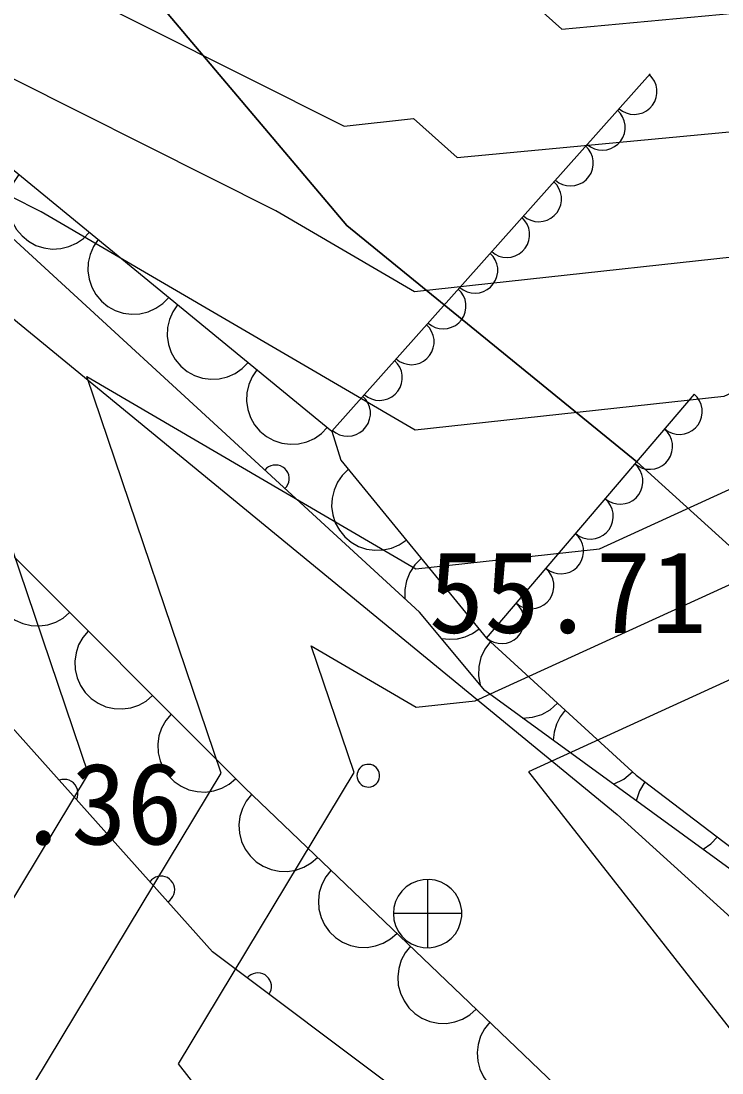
# Model space of a CAD drawing. Extents: x 42655 to 43811, y -141820 to -141156.
# Drawn here: x 43576.76 to 43584.45, y -141334.52 to -141322.99 of the extents above; entities that cross this region are included whole.
import ezdxf

# ---------------------------------------------------------------- set-up
doc = ezdxf.new("R2010")
doc.units = 0
for name, color, linetype in [('ZE_HICN', 7, 'Continuous'), ('ZE_LWCN', 7, 'Continuous'), ('地形', 7, 'Continuous'), ('現況道路ﾊｯﾁ', 7, 'Continuous')]:
    doc.layers.add(name, color=color, linetype=linetype)

msp = doc.modelspace()

# ---------------------------------------------------------------- linework, layer by layer
at = {"layer": 'ZE_HICN'}
for points in [[(43575.961, -141320.664), (43578.437, -141321.907), (43581.054, -141321.617), (43582.691, -141323.083), (43586.147, -141322.758), (43588.327, -141325.031), (43591.26, -141327.956), (43593.815, -141328.074), (43596.36, -141330.457), (43599.722, -141331.14), (43601.308, -141331.307), (43601.453, -141331.47), (43601.798, -141331.547), (43606.54, -141331.261), (43609.315, -141331.094), (43609.495, -141328.525), (43611.611, -141327.659), (43611.864, -141325.239), (43611.99, -141324.919), (43616.658, -141318.98), (43616.768, -141318.867), (43616.765, -141318.733), (43621.029, -141317.85)], [(43580.804, -141337.392), (43578.487, -141334.423), (43580.414, -141331.231), (43579.943, -141329.841), (43581.096, -141330.515), (43581.74, -141330.444), (43586.174, -141328.42), (43588.867, -141331.191), (43587.229, -141336.129), (43591.289, -141333.965), (43595.09, -141335.755)]]:
    msp.add_lwpolyline(points, dxfattribs=at)
at = {"layer": 'ZE_LWCN'}
for points in [[(43575.967, -141321.969), (43580.305, -141324.147), (43581.066, -141324.063), (43581.542, -141324.489), (43586.154, -141324.055), (43587.095, -141325.037), (43591.266, -141329.196), (43592.838, -141329.269), (43594.862, -141331.163), (43596.367, -141331.908), (43600.463, -141332.34), (43601.463, -141333.465), (43603.837, -141333.993), (43606.553, -141333.829), (43609.529, -141333.65), (43611.64, -141333.708), (43615.783, -141336.067), (43616.732, -141334.455), (43618.662, -141333.393), (43621.813, -141332.893)], [(43620.95, -141338.277), (43616.752, -141338.623), (43615.326, -141338.957), (43613.001, -141337.239), (43611.653, -141336.472), (43607.32, -141336.351), (43606.565, -141336.397), (43605.876, -141336.438), (43601.472, -141335.459), (43599.619, -141333.373), (43596.372, -141333.03), (43592.62, -141331.173), (43591.862, -141330.463), (43591.272, -141330.436), (43587.62, -141326.795), (43586.159, -141325.292), (43585.831, -141325.442), (43581.075, -141325.961), (43579.554, -141325.073), (43575.974, -141323.275)], [(43621.85, -141340.745), (43619.374, -141340.204), (43616.76, -141340.42), (43613.506, -141341.183), (43611.669, -141339.825), (43608.603, -141339.71), (43606.575, -141338.663), (43605.437, -141338.654), (43601.482, -141337.502), (43601.34, -141337.295), (43598.774, -141334.406), (43596.378, -141334.153), (43591.911, -141331.942), (43591.278, -141331.644), (43590.601, -141332.005), (43590.874, -141331.182), (43586.164, -141326.334), (43584.467, -141327.109), (43581.082, -141327.479), (43576.984, -141325.085), (43575.98, -141324.58)], [(43575.99, -141326.794), (43577.499, -141331.245), (43576.023, -141333.688)], [(43576.034, -141336.077), (43578.956, -141331.238), (43577.483, -141326.89), (43581.089, -141328.997), (43583.104, -141328.777), (43586.169, -141327.377), (43589.871, -141331.186), (43588.915, -141334.067), (43591.283, -141332.804), (43593.5, -141333.849), (43596.383, -141335.275), (43597.93, -141335.438), (43599.586, -141337.303), (43601.494, -141340.102), (43603.722, -141340.751), (43606.586, -141340.773), (43611.686, -141343.408), (43616.769, -141342.216), (43617.799, -141342.131), (43621.861, -141343.019)], [(43586.211, -141336.176), (43587.863, -141331.196), (43586.179, -141329.462), (43582.325, -141331.222), (43586.211, -141336.176)]]:
    msp.add_lwpolyline(points, dxfattribs=at)
at = {"layer": '地形'}
for p, q in [((43580.168, -141327.49), (43583.659, -141323.571)), ((43581.867, -141329.758), (43584.144, -141327.084)), ((43581.22, -141332.402), (43581.22, -141333.152)), ((43581.595, -141332.777), (43580.845, -141332.777))]:
    msp.add_line(p, q, dxfattribs=at)
for points in [[(43574.814, -141313.867), (43574.061, -141317.628), (43574.061, -141320.219), (43575.232, -141321.221), (43578.075, -141322.559), (43580.334, -141325.233), (43583.512, -141327.824), (43587.108, -141331.083), (43590.621, -141333.256), (43593.13, -141335.847), (43595.388, -141337.853), (43597.145, -141339.273), (43600.239, -141342.199), (43602.999, -141344.204), (43606.261, -141344.873), (43611.781, -141345.207), (43621.483, -141345.458)], [(43549.208, -141319.961), (43556.867, -141320.753), (43567.431, -141322.178), (43571.973, -141322.864), (43574.086, -141324.131), (43583.297, -141331.692), (43590.642, -141338.347), (43593.759, -141341.303), (43600.265, -141345.426), (43603.065, -141346.799), (43608.248, -141348.229), (43613.847, -141348.387), (43631.813, -141349.201), (43653.781, -141346.583), (43661.115, -141345.834), (43670.949, -141346.829), (43671.768, -141347.675)], [(43628.738, -141345.821), (43620.496, -141346.308), (43614.344, -141346.486), (43609.411, -141345.917), (43606.922, -141345.575), (43602.787, -141344.666), (43600.173, -141343.368), (43595.089, -141339.575), (43593.827, -141338.836), (43587.334, -141334.324), (43581.848, -141330.333), (43581.132, -141329.474), (43575.037, -141323.875), (43570.779, -141321.115)], [(43570.779, -141321.115), (43574.951, -141323.21), (43580.168, -141327.49), (43580.267, -141327.808), (43581.867, -141329.758), (43583.506, -141331.26), (43587.441, -141334.255), (43594.296, -141338.759), (43595.901, -141339.354), (43600.766, -141339.448), (43599.883, -141340.118), (43596.038, -141339.881), (43595.089, -141339.575), (43593.827, -141338.836), (43587.334, -141334.324), (43581.848, -141330.333), (43581.132, -141329.474), (43575.037, -141323.875), (43570.779, -141321.115)], [(43568.974, -141323.194), (43571.629, -141325.072), (43576.487, -141328.669), (43579.216, -141331.4), (43582.697, -141334.729), (43585.548, -141336.778), (43591.025, -141340.112), (43586.316, -141338.226), (43583.02, -141336.315), (43578.862, -141333.197), (43574.52, -141328.339), (43572.263, -141326.29), (43569.243, -141324.151), (43568.974, -141323.851)], [(43583.318, -141323.954), (43583.355, -141323.981), (43583.397, -141324.001), (43583.441, -141324.013), (43583.487, -141324.017), (43583.533, -141324.012), (43583.578, -141323.999), (43583.619, -141323.978), (43583.655, -141323.95), (43583.686, -141323.916), (43583.71, -141323.876), (43583.726, -141323.833), (43583.734, -141323.787), (43583.733, -141323.741), (43583.724, -141323.696), (43583.707, -141323.653), (43583.682, -141323.614), (43583.651, -141323.58)], [(43582.969, -141324.346), (43583.006, -141324.373), (43583.048, -141324.393), (43583.092, -141324.405), (43583.138, -141324.409), (43583.184, -141324.404), (43583.229, -141324.391), (43583.27, -141324.37), (43583.306, -141324.342), (43583.337, -141324.307), (43583.361, -141324.268), (43583.377, -141324.225), (43583.385, -141324.179), (43583.384, -141324.133), (43583.375, -141324.088), (43583.358, -141324.045), (43583.333, -141324.006), (43583.302, -141323.972)], [(43582.62, -141324.738), (43582.657, -141324.765), (43582.699, -141324.785), (43582.743, -141324.797), (43582.789, -141324.801), (43582.835, -141324.796), (43582.879, -141324.783), (43582.92, -141324.762), (43582.957, -141324.734), (43582.988, -141324.699), (43583.012, -141324.66), (43583.028, -141324.616), (43583.036, -141324.571), (43583.035, -141324.525), (43583.026, -141324.48), (43583.009, -141324.437), (43582.984, -141324.398), (43582.953, -141324.364)], [(43576.738, -141324.676), (43576.686, -141324.753), (43576.65, -141324.837), (43576.629, -141324.927), (43576.625, -141325.019), (43576.639, -141325.111), (43576.669, -141325.198), (43576.714, -141325.278), (43576.773, -141325.349), (43576.845, -141325.407), (43576.926, -141325.452), (43577.013, -141325.481), (43577.105, -141325.493), (43577.197, -141325.488), (43577.287, -141325.466), (43577.371, -141325.429), (43577.447, -141325.376), (43577.511, -141325.31)], [(43582.271, -141325.129), (43582.308, -141325.157), (43582.35, -141325.177), (43582.394, -141325.189), (43582.44, -141325.193), (43582.486, -141325.188), (43582.53, -141325.175), (43582.571, -141325.154), (43582.608, -141325.126), (43582.639, -141325.091), (43582.662, -141325.052), (43582.679, -141325.008), (43582.687, -141324.963), (43582.686, -141324.917), (43582.677, -141324.872), (43582.66, -141324.829), (43582.635, -141324.79), (43582.604, -141324.756)], [(43581.922, -141325.521), (43581.959, -141325.549), (43582.001, -141325.569), (43582.045, -141325.581), (43582.091, -141325.585), (43582.137, -141325.58), (43582.181, -141325.567), (43582.222, -141325.546), (43582.259, -141325.517), (43582.29, -141325.483), (43582.313, -141325.443), (43582.33, -141325.4), (43582.338, -141325.355), (43582.337, -141325.309), (43582.328, -141325.263), (43582.311, -141325.221), (43582.286, -141325.182), (43582.255, -141325.148)], [(43577.608, -141325.389), (43577.556, -141325.466), (43577.519, -141325.551), (43577.499, -141325.64), (43577.495, -141325.733), (43577.508, -141325.824), (43577.538, -141325.911), (43577.584, -141325.992), (43577.643, -141326.062), (43577.714, -141326.121), (43577.795, -141326.165), (43577.883, -141326.194), (43577.974, -141326.206), (43578.066, -141326.201), (43578.156, -141326.18), (43578.24, -141326.142), (43578.316, -141326.089), (43578.381, -141326.024)], [(43581.573, -141325.913), (43581.61, -141325.94), (43581.652, -141325.961), (43581.696, -141325.973), (43581.742, -141325.976), (43581.788, -141325.972), (43581.832, -141325.958), (43581.873, -141325.937), (43581.91, -141325.909), (43581.94, -141325.875), (43581.964, -141325.835), (43581.98, -141325.792), (43581.988, -141325.747), (43581.988, -141325.7), (43581.979, -141325.655), (43581.962, -141325.612), (43581.937, -141325.573), (43581.906, -141325.54)], [(43581.224, -141326.305), (43581.261, -141326.332), (43581.303, -141326.352), (43581.347, -141326.365), (43581.393, -141326.368), (43581.439, -141326.363), (43581.483, -141326.35), (43581.524, -141326.329), (43581.561, -141326.301), (43581.591, -141326.267), (43581.615, -141326.227), (43581.631, -141326.184), (43581.639, -141326.138), (43581.639, -141326.092), (43581.63, -141326.047), (43581.613, -141326.004), (43581.588, -141325.965), (43581.556, -141325.932)], [(43578.477, -141326.103), (43578.426, -141326.179), (43578.389, -141326.264), (43578.368, -141326.354), (43578.365, -141326.446), (43578.378, -141326.537), (43578.408, -141326.625), (43578.453, -141326.705), (43578.513, -141326.776), (43578.584, -141326.834), (43578.665, -141326.878), (43578.753, -141326.907), (43578.844, -141326.919), (43578.936, -141326.915), (43579.026, -141326.893), (43579.11, -141326.855), (43579.186, -141326.803), (43579.251, -141326.737)], [(43580.875, -141326.697), (43580.912, -141326.724), (43580.954, -141326.744), (43580.998, -141326.756), (43581.044, -141326.76), (43581.09, -141326.755), (43581.134, -141326.742), (43581.175, -141326.721), (43581.212, -141326.693), (43581.242, -141326.658), (43581.266, -141326.619), (43581.282, -141326.576), (43581.29, -141326.53), (43581.29, -141326.484), (43581.281, -141326.439), (43581.264, -141326.396), (43581.239, -141326.357), (43581.207, -141326.323)], [(43580.526, -141327.089), (43580.563, -141327.116), (43580.604, -141327.136), (43580.649, -141327.148), (43580.695, -141327.152), (43580.741, -141327.147), (43580.785, -141327.134), (43580.826, -141327.113), (43580.863, -141327.085), (43580.893, -141327.05), (43580.917, -141327.011), (43580.933, -141326.968), (43580.941, -141326.922), (43580.941, -141326.876), (43580.932, -141326.831), (43580.915, -141326.788), (43580.89, -141326.749), (43580.858, -141326.715)], [(43579.347, -141326.816), (43579.295, -141326.892), (43579.259, -141326.977), (43579.238, -141327.067), (43579.234, -141327.159), (43579.248, -141327.251), (43579.277, -141327.338), (43579.323, -141327.418), (43579.382, -141327.489), (43579.454, -141327.547), (43579.534, -141327.592), (43579.622, -141327.621), (43579.714, -141327.633), (43579.806, -141327.628), (43579.895, -141327.606), (43579.98, -141327.568), (43580.055, -141327.516), (43580.12, -141327.45)], [(43580.177, -141327.48), (43580.214, -141327.508), (43580.255, -141327.528), (43580.3, -141327.54), (43580.346, -141327.544), (43580.392, -141327.539), (43580.436, -141327.526), (43580.477, -141327.505), (43580.514, -141327.477), (43580.544, -141327.442), (43580.568, -141327.403), (43580.584, -141327.359), (43580.592, -141327.314), (43580.592, -141327.268), (43580.583, -141327.223), (43580.565, -141327.18), (43580.541, -141327.141), (43580.509, -141327.107)], [(43583.819, -141327.465), (43583.857, -141327.492), (43583.899, -141327.511), (43583.943, -141327.522), (43583.99, -141327.525), (43584.035, -141327.519), (43584.079, -141327.505), (43584.12, -141327.483), (43584.156, -141327.454), (43584.186, -141327.418), (43584.208, -141327.378), (43584.224, -141327.335), (43584.231, -141327.289), (43584.229, -141327.243), (43584.219, -141327.198), (43584.201, -141327.156), (43584.175, -141327.117), (43584.143, -141327.084)], [(43583.494, -141327.847), (43583.531, -141327.874), (43583.573, -141327.893), (43583.618, -141327.904), (43583.664, -141327.907), (43583.71, -141327.901), (43583.754, -141327.887), (43583.795, -141327.865), (43583.83, -141327.836), (43583.86, -141327.801), (43583.883, -141327.761), (43583.898, -141327.717), (43583.905, -141327.671), (43583.904, -141327.625), (43583.894, -141327.58), (43583.876, -141327.538), (43583.85, -141327.499), (43583.818, -141327.466)], [(43579.656, -141328.118), (43579.674, -141328.098), (43579.688, -141328.074), (43579.698, -141328.049), (43579.702, -141328.022), (43579.702, -141327.995), (43579.697, -141327.968), (43579.687, -141327.943), (43579.673, -141327.919), (43579.654, -141327.899), (43579.633, -141327.883), (43579.608, -141327.87), (43579.582, -141327.862), (43579.555, -141327.86), (43579.528, -141327.862), (43579.501, -141327.869), (43579.477, -141327.88), (43579.455, -141327.896), (43579.436, -141327.916)], [(43580.35, -141327.909), (43580.284, -141327.974), (43580.231, -141328.049), (43580.194, -141328.134), (43580.172, -141328.223), (43580.167, -141328.315), (43580.179, -141328.407), (43580.208, -141328.495), (43580.253, -141328.575), (43580.311, -141328.647), (43580.382, -141328.706), (43580.462, -141328.752), (43580.549, -141328.781), (43580.641, -141328.795), (43580.733, -141328.791), (43580.823, -141328.77), (43580.907, -141328.734), (43580.984, -141328.682)], [(43583.168, -141328.229), (43583.206, -141328.256), (43583.248, -141328.275), (43583.293, -141328.286), (43583.339, -141328.289), (43583.385, -141328.283), (43583.429, -141328.269), (43583.469, -141328.247), (43583.505, -141328.218), (43583.535, -141328.183), (43583.558, -141328.143), (43583.573, -141328.099), (43583.58, -141328.053), (43583.579, -141328.007), (43583.569, -141327.962), (43583.55, -141327.92), (43583.525, -141327.881), (43583.493, -141327.848)], [(43582.843, -141328.611), (43582.881, -141328.638), (43582.923, -141328.657), (43582.968, -141328.668), (43583.014, -141328.671), (43583.06, -141328.665), (43583.103, -141328.651), (43583.144, -141328.629), (43583.18, -141328.6), (43583.21, -141328.565), (43583.233, -141328.525), (43583.248, -141328.481), (43583.255, -141328.435), (43583.253, -141328.389), (43583.243, -141328.344), (43583.225, -141328.302), (43583.2, -141328.264), (43583.167, -141328.231)], [(43582.518, -141328.993), (43582.556, -141329.02), (43582.598, -141329.039), (43582.642, -141329.05), (43582.689, -141329.053), (43582.734, -141329.047), (43582.778, -141329.033), (43582.819, -141329.011), (43582.855, -141328.982), (43582.885, -141328.947), (43582.907, -141328.907), (43582.923, -141328.863), (43582.93, -141328.818), (43582.928, -141328.771), (43582.918, -141328.726), (43582.9, -141328.684), (43582.874, -141328.646), (43582.842, -141328.613)], [(43576.588, -141328.771), (43576.529, -141328.842), (43576.485, -141328.922), (43576.455, -141329.01), (43576.442, -141329.101), (43576.447, -141329.193), (43576.468, -141329.283), (43576.505, -141329.368), (43576.557, -141329.444), (43576.622, -141329.509), (43576.698, -141329.561), (43576.783, -141329.598), (43576.873, -141329.62), (43576.965, -141329.624), (43577.056, -141329.611), (43577.144, -141329.582), (43577.224, -141329.537), (43577.295, -141329.478)], [(43581.15, -141328.884), (43581.08, -141328.954), (43581.025, -141329.037), (43580.987, -141329.129), (43580.969, -141329.226), (43580.97, -141329.326)], [(43582.193, -141329.375), (43582.23, -141329.402), (43582.272, -141329.421), (43582.317, -141329.432), (43582.363, -141329.435), (43582.409, -141329.429), (43582.453, -141329.415), (43582.494, -141329.393), (43582.529, -141329.364), (43582.559, -141329.329), (43582.582, -141329.289), (43582.597, -141329.245), (43582.604, -141329.2), (43582.603, -141329.154), (43582.593, -141329.109), (43582.575, -141329.066), (43582.549, -141329.028), (43582.517, -141328.995)], [(43581.868, -141329.758), (43581.905, -141329.784), (43581.947, -141329.803), (43581.992, -141329.814), (43582.038, -141329.817), (43582.084, -141329.811), (43582.128, -141329.797), (43582.168, -141329.775), (43582.204, -141329.746), (43582.234, -141329.711), (43582.257, -141329.671), (43582.272, -141329.627), (43582.279, -141329.582), (43582.278, -141329.536), (43582.268, -141329.491), (43582.249, -141329.448), (43582.224, -141329.41), (43582.192, -141329.377)], [(43581.371, -141329.761), (43581.459, -141329.77), (43581.546, -141329.764), (43581.631, -141329.743), (43581.711, -141329.707), (43581.784, -141329.657)], [(43577.498, -141329.681), (43577.439, -141329.752), (43577.394, -141329.832), (43577.365, -141329.92), (43577.352, -141330.011), (43577.356, -141330.103), (43577.377, -141330.193), (43577.415, -141330.278), (43577.467, -141330.354), (43577.532, -141330.419), (43577.608, -141330.471), (43577.692, -141330.509), (43577.782, -141330.53), (43577.874, -141330.534), (43577.966, -141330.521), (43578.053, -141330.492), (43578.134, -141330.447), (43578.205, -141330.388)], [(43581.908, -141329.796), (43581.847, -141329.877), (43581.804, -141329.97), (43581.781, -141330.068), (43581.778, -141330.17), (43581.796, -141330.27)], [(43582.261, -141330.633), (43582.368, -141330.625), (43582.471, -141330.594), (43582.565, -141330.542), (43582.645, -141330.471)], [(43582.728, -141330.547), (43582.673, -141330.619), (43582.632, -141330.7), (43582.606, -141330.787), (43582.596, -141330.877)], [(43578.408, -141330.591), (43578.349, -141330.662), (43578.304, -141330.743), (43578.274, -141330.83), (43578.262, -141330.921), (43578.266, -141331.014), (43578.287, -141331.103), (43578.324, -141331.188), (43578.376, -141331.264), (43578.442, -141331.329), (43578.518, -141331.381), (43578.602, -141331.419), (43578.692, -141331.44), (43578.784, -141331.444), (43578.876, -141331.431), (43578.963, -141331.402), (43579.044, -141331.357), (43579.115, -141331.298)], [(43580.445, -141331.265), (43580.447, -141331.288), (43580.453, -141331.309), (43580.463, -141331.33), (43580.476, -141331.348), (43580.492, -141331.363), (43580.511, -141331.376), (43580.531, -141331.384), (43580.553, -141331.389), (43580.576, -141331.39), (43580.598, -141331.387), (43580.619, -141331.38), (43580.639, -141331.37), (43580.656, -141331.356), (43580.671, -141331.339), (43580.683, -141331.32), (43580.69, -141331.299), (43580.694, -141331.277), (43580.694, -141331.254), (43580.69, -141331.232), (43580.683, -141331.211), (43580.671, -141331.192), (43580.656, -141331.175), (43580.639, -141331.161), (43580.619, -141331.151), (43580.598, -141331.144), (43580.576, -141331.141), (43580.553, -141331.142), (43580.531, -141331.147), (43580.511, -141331.155), (43580.492, -141331.168), (43580.476, -141331.183), (43580.463, -141331.201), (43580.453, -141331.222), (43580.447, -141331.243), (43580.445, -141331.265)], [(43583.257, -141331.358), (43583.37, -141331.303), (43583.465, -141331.222)], [(43577.369, -141331.526), (43577.38, -141331.5), (43577.386, -141331.473), (43577.386, -141331.445), (43577.382, -141331.417), (43577.372, -141331.391), (43577.357, -141331.366), (43577.339, -141331.345), (43577.316, -141331.328), (43577.291, -141331.316), (43577.264, -141331.308), (43577.236, -141331.306), (43577.208, -141331.308), (43577.181, -141331.316)], [(43583.6, -141331.332), (43583.542, -141331.43), (43583.507, -141331.54)], [(43579.29, -141331.47), (43579.232, -141331.543), (43579.189, -141331.624), (43579.162, -141331.712), (43579.151, -141331.804), (43579.158, -141331.896), (43579.181, -141331.985), (43579.22, -141332.069), (43579.274, -141332.144), (43579.34, -141332.208), (43579.418, -141332.258), (43579.503, -141332.293), (43579.593, -141332.313), (43579.685, -141332.315), (43579.776, -141332.3), (43579.863, -141332.269), (43579.943, -141332.222), (43580.012, -141332.162)], [(43584.24, -141332.072), (43584.325, -141332.013), (43584.396, -141331.937)], [(43580.16, -141332.303), (43580.103, -141332.375), (43580.06, -141332.457), (43580.032, -141332.545), (43580.022, -141332.636), (43580.028, -141332.728), (43580.051, -141332.818), (43580.09, -141332.901), (43580.144, -141332.976), (43580.211, -141333.04), (43580.288, -141333.091), (43580.373, -141333.126), (43580.463, -141333.145), (43580.556, -141333.147), (43580.647, -141333.132), (43580.734, -141333.101), (43580.813, -141333.055), (43580.883, -141332.994)], [(43578.371, -141332.647), (43578.393, -141332.632), (43578.412, -141332.613), (43578.427, -141332.591), (43578.439, -141332.567), (43578.445, -141332.541), (43578.447, -141332.514), (43578.445, -141332.487), (43578.437, -141332.462), (43578.425, -141332.438), (43578.409, -141332.416), (43578.39, -141332.398), (43578.367, -141332.383), (43578.342, -141332.373), (43578.316, -141332.367), (43578.29, -141332.366), (43578.263, -141332.37), (43578.238, -141332.379), (43578.214, -141332.391), (43578.193, -141332.408), (43578.176, -141332.428)], [(43580.845, -141332.777), (43580.851, -141332.844), (43580.869, -141332.908), (43580.898, -141332.969), (43580.938, -141333.023), (43580.986, -141333.07), (43581.043, -141333.107), (43581.104, -141333.133), (43581.17, -141333.148), (43581.237, -141333.151), (43581.304, -141333.142), (43581.368, -141333.121), (43581.427, -141333.089), (43581.479, -141333.048), (43581.524, -141332.997), (43581.558, -141332.939), (43581.582, -141332.876), (43581.594, -141332.81), (43581.594, -141332.743), (43581.582, -141332.677), (43581.558, -141332.614), (43581.524, -141332.556), (43581.479, -141332.505), (43581.427, -141332.464), (43581.368, -141332.432), (43581.304, -141332.411), (43581.237, -141332.402), (43581.17, -141332.405), (43581.104, -141332.42), (43581.043, -141332.446), (43580.986, -141332.483), (43580.938, -141332.53), (43580.898, -141332.584), (43580.869, -141332.645), (43580.851, -141332.71), (43580.845, -141332.777)], [(43581.031, -141333.135), (43580.973, -141333.208), (43580.93, -141333.289), (43580.903, -141333.377), (43580.892, -141333.469), (43580.898, -141333.561), (43580.921, -141333.65), (43580.961, -141333.734), (43581.014, -141333.809), (43581.081, -141333.873), (43581.158, -141333.923), (43581.244, -141333.958), (43581.334, -141333.977), (43581.426, -141333.98), (43581.517, -141333.965), (43581.604, -141333.934), (43581.684, -141333.887), (43581.753, -141333.826)], [(43579.482, -141333.661), (43579.495, -141333.638), (43579.504, -141333.612), (43579.508, -141333.586), (43579.507, -141333.559), (43579.501, -141333.533), (43579.491, -141333.508), (43579.477, -141333.485), (43579.458, -141333.465), (43579.437, -141333.449), (43579.413, -141333.437), (43579.387, -141333.43), (43579.36, -141333.427), (43579.334, -141333.429), (43579.308, -141333.436), (43579.283, -141333.447), (43579.261, -141333.462), (43579.242, -141333.481)], [(43581.901, -141333.968), (43581.844, -141334.04), (43581.8, -141334.122), (43581.773, -141334.21), (43581.762, -141334.301), (43581.769, -141334.393), (43581.792, -141334.483), (43581.831, -141334.566), (43581.885, -141334.641), (43581.951, -141334.705), (43582.029, -141334.755), (43582.114, -141334.791), (43582.204, -141334.81), (43582.296, -141334.812), (43582.387, -141334.797), (43582.474, -141334.766), (43582.554, -141334.719), (43582.624, -141334.659)]]:
    msp.add_lwpolyline(points, dxfattribs=at)
at = {"layer": '現況道路ﾊｯﾁ'}
for points in [[(43621.483, -141345.458), (43611.781, -141345.207), (43606.261, -141344.873), (43602.999, -141344.204), (43600.239, -141342.199), (43597.145, -141339.273), (43595.388, -141337.853), (43593.13, -141335.847), (43590.621, -141333.256), (43587.108, -141331.083), (43583.512, -141327.824), (43580.334, -141325.233), (43578.075, -141322.559), (43575.232, -141321.221), (43574.061, -141320.219), (43574.061, -141317.628), (43574.814, -141313.867)], [(43549.208, -141319.961), (43556.867, -141320.753), (43567.431, -141322.178), (43571.973, -141322.864), (43574.086, -141324.131), (43583.297, -141331.692), (43590.642, -141338.347), (43593.759, -141341.303), (43600.265, -141345.426), (43603.065, -141346.799), (43608.248, -141348.229), (43613.847, -141348.387), (43631.813, -141349.201)]]:
    msp.add_lwpolyline(points, dxfattribs=at)

# ---------------------------------------------------------------- texts
at = {"layer": '地形'}
for s, p in [('55.71', (43581.231, -141329.7)), ('52.36', (43575.483, -141332.019))]:
    msp.add_text(s, height=0.8962, dxfattribs=at).set_placement(p)

doc.saveas('drawing.dxf')
